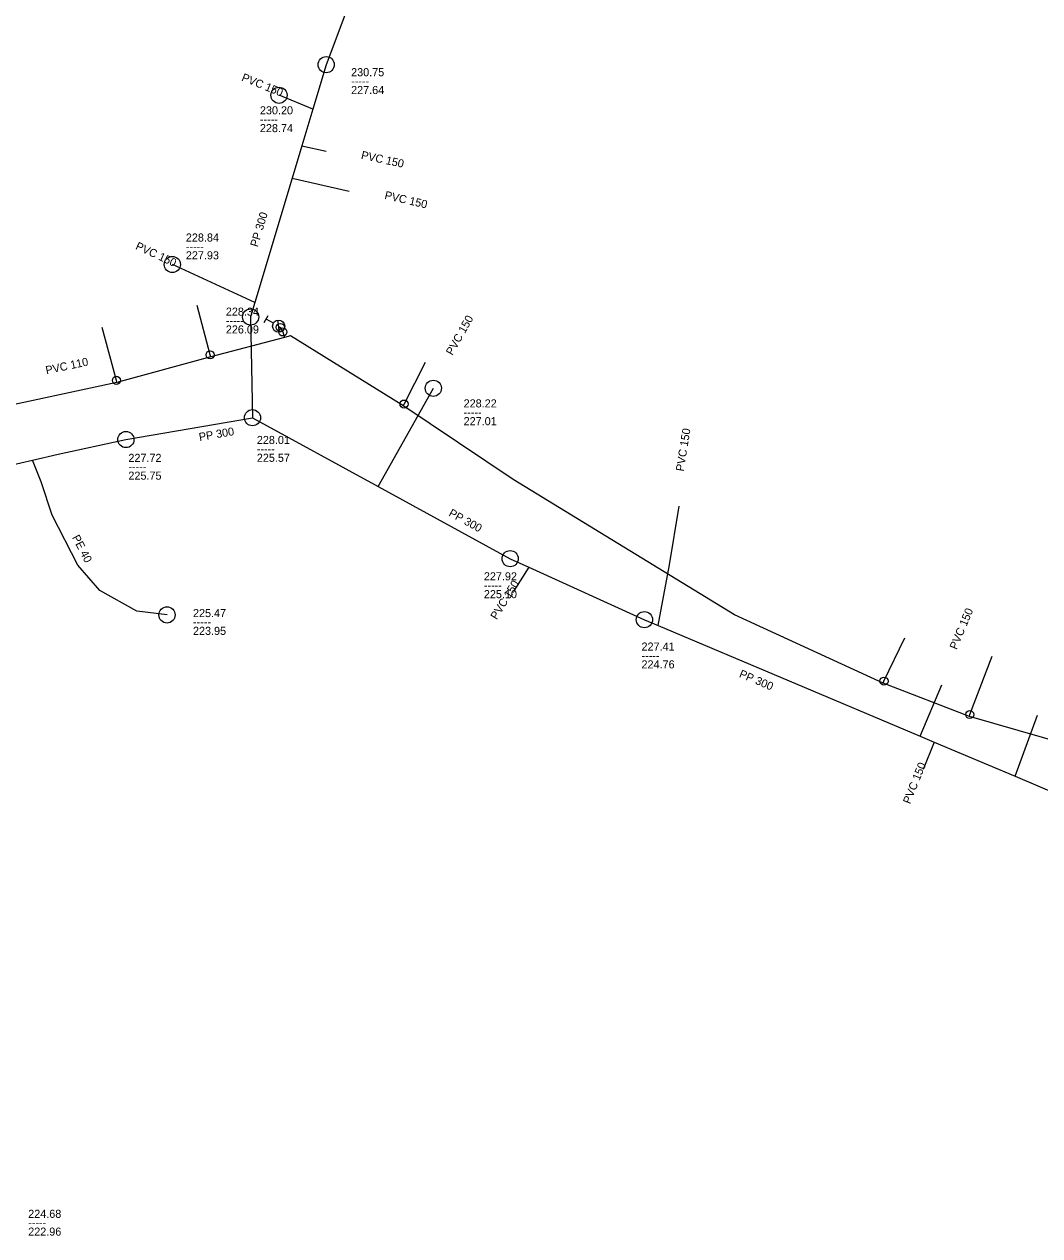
# Model space of a CAD drawing. Extents: x -771212 to -769571, y -1050452 to -1050119.
# Drawn here: x -770815.2 to -770689.8, y -1050389.5 to -1050239.8 of the extents above; entities that cross this region are included whole.
import ezdxf

# ---------------------------------------------------------------- set-up
doc = ezdxf.new("R2010")
doc.units = 0
doc.layers.add('Level 0', color=7, linetype='Continuous')

msp = doc.modelspace()

# ---------------------------------------------------------------- linework, layer by layer
at = {"layer": 'Level 0'}
for p, q in [((-770775.11, -1050237.31), (-770777.92, -1050244.75)), ((-770777.92, -1050244.75), (-770779.56, -1050250.23)), ((-770779.56, -1050250.23), (-770783.75, -1050248.53)), ((-770779.56, -1050250.23), (-770780.93, -1050254.79)), ((-770780.93, -1050254.79), (-770782.12, -1050258.77)), ((-770780.93, -1050254.79), (-770777.92, -1050255.44)), ((-770782.12, -1050258.77), (-770786.73, -1050274.16)), ((-770782.12, -1050258.77), (-770775.1, -1050260.4)), ((-770786.73, -1050274.16), (-770796.93, -1050269.44)), ((-770792.26, -1050280.61), (-770793.88, -1050274.5)), ((-770786.73, -1050274.16), (-770787.26, -1050275.93)), ((-770787.26, -1050275.93), (-770787.03, -1050288.38)), ((-770785.57, -1050276.62), (-770785.07, -1050275.75)), ((-770784.45, -1050276.69), (-770785.32, -1050276.19)), ((-770783.69, -1050277.8), (-770783.91, -1050276.32)), ((-770803.84, -1050283.76), (-770805.6, -1050277.24)), ((-770783.8, -1050277.06), (-770783.59, -1050277.22)), ((-770783.59, -1050277.22), (-770783.28, -1050277.78)), ((-770783.28, -1050277.78), (-770783.09, -1050278.48)), ((-770783.09, -1050278.48), (-770792.17, -1050280.85)), ((-770782.33, -1050278.28), (-770783.09, -1050278.48)), ((-770768.47, -1050286.88), (-770782.33, -1050278.28)), ((-770792.17, -1050280.85), (-770803.78, -1050284.02)), ((-770792.17, -1050280.85), (-770792.26, -1050280.61)), ((-770768.3, -1050286.69), (-770765.63, -1050281.52)), ((-770803.78, -1050284.02), (-770821.6, -1050287.84)), ((-770803.78, -1050284.02), (-770803.84, -1050283.76)), ((-770771.51, -1050296.87), (-770764.68, -1050284.74)), ((-770768.47, -1050286.88), (-770768.3, -1050286.69)), ((-770754.83, -1050296.01), (-770768.47, -1050286.88)), ((-770802.67, -1050291.08), (-770787.03, -1050288.38)), ((-770787.03, -1050288.38), (-770771.51, -1050296.87)), ((-770811.05, -1050292.89), (-770802.67, -1050291.08)), ((-770814.21, -1050293.62), (-770811.05, -1050292.89)), ((-770820.42, -1050295.05), (-770814.21, -1050293.62)), ((-770813.13, -1050296.32), (-770814.21, -1050293.62)), ((-770811.78, -1050300.44), (-770813.13, -1050296.32)), ((-770771.51, -1050296.87), (-770755.19, -1050305.8)), ((-770727.47, -1050312.73), (-770754.83, -1050296.01)), ((-770808.61, -1050306.59), (-770811.78, -1050300.44)), ((-770735.49, -1050306.57), (-770734.32, -1050299.31)), ((-770755.19, -1050305.8), (-770752.89, -1050306.84)), ((-770805.89, -1050309.75), (-770808.61, -1050306.59)), ((-770752.89, -1050306.84), (-770754.72, -1050309.79)), ((-770752.89, -1050306.84), (-770738.6, -1050313.34)), ((-770736.92, -1050314.05), (-770735.49, -1050306.57)), ((-770801.32, -1050312.29), (-770805.89, -1050309.75)), ((-770797.59, -1050312.75), (-770801.32, -1050312.29)), ((-770738.6, -1050313.34), (-770736.92, -1050314.05)), ((-770709.11, -1050321.17), (-770727.47, -1050312.73)), ((-770736.92, -1050314.05), (-770704.54, -1050327.73)), ((-770709, -1050320.93), (-770706.41, -1050315.58)), ((-770698.4, -1050325.06), (-770695.63, -1050317.86)), ((-770709.11, -1050321.17), (-770709, -1050320.93)), ((-770698.44, -1050325.32), (-770709.11, -1050321.17)), ((-770704.54, -1050327.73), (-770701.87, -1050321.38)), ((-770698.44, -1050325.32), (-770698.4, -1050325.06)), ((-770663.54, -1050335.3), (-770698.44, -1050325.32)), ((-770692.81, -1050332.69), (-770690.05, -1050325.14)), ((-770704.54, -1050327.73), (-770702.79, -1050328.47)), ((-770702.79, -1050328.47), (-770704.15, -1050331.87)), ((-770702.79, -1050328.47), (-770692.81, -1050332.69)), ((-770692.81, -1050332.69), (-770687.49, -1050334.94))]:
    msp.add_line(p, q, dxfattribs=at)
for centre, radius in [((-770777.92, -1050244.75), 1), ((-770783.75, -1050248.53), 1), ((-770796.93, -1050269.44), 1), ((-770787.26, -1050275.93), 1), ((-770783.8, -1050277.06), 0.75), ((-770783.59, -1050277.22), 0.5), ((-770783.28, -1050277.78), 0.5), ((-770792.26, -1050280.61), 0.5), ((-770803.84, -1050283.76), 0.5), ((-770764.68, -1050284.74), 1), ((-770768.3, -1050286.69), 0.5), ((-770787.03, -1050288.38), 1), ((-770802.67, -1050291.08), 1), ((-770755.19, -1050305.8), 1), ((-770797.59, -1050312.75), 1), ((-770738.6, -1050313.34), 1), ((-770709, -1050320.93), 0.5), ((-770698.4, -1050325.06), 0.5)]:
    msp.add_circle(centre, radius, dxfattribs=at)

# ---------------------------------------------------------------- texts
for s, rotation, p in [('PVC 150', 337.916, (-770788.46, -1050246.7)), ('PVC 150', 347.814, (-770773.67, -1050256.37)), ('PVC 150', 346.928, (-770770.77, -1050261.32)), ('PP 300', 73.354, (-770786.38, -1050267.35)), ('PVC 150', 335.168, (-770801.57, -1050267.51)), ('PVC 150', 60.618, (-770762.32, -1050280.75)), ('PVC 110', 12.002, (-770812.48, -1050283.02)), ('PP 300', 9.795, (-770793.56, -1050291.27)), ('PVC 150', 80.845, (-770733.75, -1050295.06)), ('PP 300', 331.313, (-770762.87, -1050300.46)), ('PE 40', 297.269, (-770809.35, -1050303.17)), ('PVC 150', 58.187, (-770756.85, -1050313.42)), ('PVC 150', 67.195, (-770700.02, -1050317.11)), ('PP 300', 337.079, (-770726.98, -1050320.4)), ('PVC 150', 68.199, (-770705.77, -1050336.19))]:
    msp.add_text(s, height=1, rotation=rotation, dxfattribs=at).set_placement(p)
for s, p in [('230.75', (-770774.84, -1050246.18)), ('-----', (-770774.84, -1050247.28)), ('227.64', (-770774.84, -1050248.38)), ('230.20', (-770786.11, -1050250.89)), ('-----', (-770786.11, -1050251.99)), ('228.74', (-770786.11, -1050253.09)), ('228.84', (-770795.26, -1050266.61)), ('-----', (-770795.26, -1050267.71)), ('227.93', (-770795.26, -1050268.81)), ('228.34', (-770790.32, -1050275.77)), ('-----', (-770790.32, -1050276.87)), ('226.09', (-770790.32, -1050277.97)), ('228.22', (-770760.94, -1050287.11)), ('-----', (-770760.94, -1050288.21)), ('227.01', (-770760.94, -1050289.31)), ('228.01', (-770786.49, -1050291.63)), ('227.72', (-770802.36, -1050293.84)), ('-----', (-770786.49, -1050292.73)), ('225.57', (-770786.49, -1050293.83)), ('-----', (-770802.36, -1050294.94)), ('225.75', (-770802.36, -1050296.04)), ('227.92', (-770758.44, -1050308.48)), ('-----', (-770758.44, -1050309.58)), ('225.10', (-770758.44, -1050310.68)), ('225.47', (-770794.38, -1050313.02)), ('-----', (-770794.38, -1050314.12)), ('223.95', (-770794.38, -1050315.22)), ('227.41', (-770738.96, -1050317.16)), ('-----', (-770738.96, -1050318.26)), ('224.76', (-770738.96, -1050319.36)), ('224.68', (-770814.74, -1050387.26)), ('-----', (-770814.74, -1050388.36)), ('222.96', (-770814.74, -1050389.46))]:
    msp.add_text(s, height=1, dxfattribs=at).set_placement(p)

doc.saveas('drawing.dxf')
